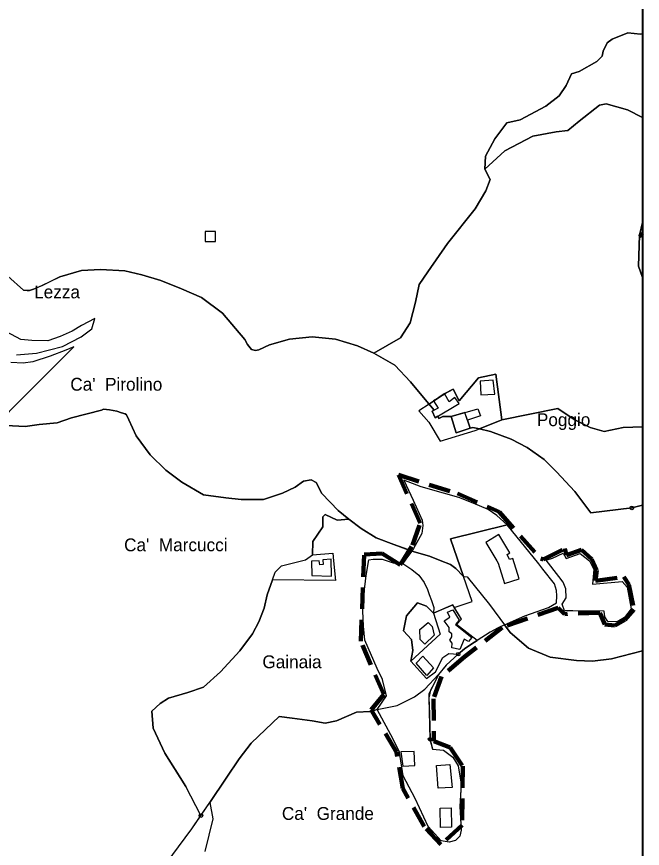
# Model space of a CAD drawing. Extents: x 652791 to 656927, y 889884 to 892405.
# Drawn here: x 656439 to 656927, y 891133 to 891781 of the extents above; entities that cross this region are included whole.
import ezdxf
from ezdxf.enums import TextEntityAlignment as Align

# ---------------------------------------------------------------- set-up
doc = ezdxf.new("R2010")
doc.units = 0
doc.header["$LTSCALE"] = 5.6
doc.header["$PDMODE"] = 32
doc.header["$PDSIZE"] = 2.8
doc.linetypes.add('MEDIUM_DASHED', pattern=[4.5, 3, -1.5])
for name, color, linetype, lineweight in [('2', 7, 'Continuous', 25), ('29', 7, 'Continuous', 25), ('3', 7, 'Continuous', 25), ('35', 7, 'Continuous', 25), ('36', 7, 'Continuous', 25), ('37', 7, 'Continuous', 25), ('55', 7, 'Continuous', 25), ('6', 7, 'Continuous', 25), ('61', 7, 'Continuous', 35), ('7', 7, 'MEDIUM_DASHED', 100), ('9', 7, 'Continuous', 25)]:
    doc.layers.add(name, color=color, linetype=linetype, lineweight=lineweight)
doc.layers.add('60', color=7, linetype='Continuous')

msp = doc.modelspace()

# ---------------------------------------------------------------- linework, layer by layer
at = {"layer": '2'}
for points in [[(656740.56, 891189.29), (656737.49, 891207.75), (656732.75, 891217.93), (656720.19, 891241.12), (656735.76, 891244.14), (656749.25, 891250.78), (656757.25, 891256.73), (656767.97, 891268.36), (656760.44, 891253.02), (656761.35, 891217.78)], [(656761.35, 891217.78), (656763.34, 891210.01), (656771.87, 891209.25), (656779.26, 891203.94), (656783.31, 891197.18), (656785.59, 891182.99), (656784.57, 891165.38), (656785.62, 891147.05)], [(656770.04, 891138.59), (656765.02, 891141.89), (656759.91, 891149.86), (656749.79, 891171.53), (656740.56, 891189.29)], [(656785.62, 891147.05), (656784.72, 891142.27), (656781.31, 891139.05), (656776.2, 891137.53), (656770.04, 891138.59)]]:
    msp.add_lwpolyline(points, dxfattribs=at)
for points in [[(656738.67, 891207.99), (656740.09, 891196.86), (656749.55, 891197.33), (656749.08, 891208.23)], [(656766.35, 891197.33), (656776.79, 891198.03), (656778.55, 891180.27), (656767.77, 891179.58)], [(656769.22, 891164.23), (656777.75, 891164.45), (656778.13, 891149.3), (656769.6, 891149.09)]]:
    msp.add_lwpolyline(points, close=True, dxfattribs=at)
at = {"layer": '29'}
msp.add_line((656807.7, 891322.7), (656819.4, 891306.96), dxfattribs=at)
for points in [[(656819.4, 891306.96), (656835.17, 891313.87), (656853.61, 891320.46), (656860.03, 891324.08), (656860.27, 891329.63), (656860.03, 891333.73), (656858.34, 891338.79), (656849.18, 891350.37), (656846.22, 891354.57), (656821.47, 891384.93), (656777.34, 891374.06), (656787.49, 891344.56)], [(656727.47, 891251.62), (656724.29, 891264.49), (656720.11, 891273.05), (656710.65, 891295.12), (656709.54, 891305.81), (656709, 891317.83), (656709.91, 891330.03), (656711.55, 891345.51), (656713.71, 891357.68)], [(656713.71, 891357.68), (656717.15, 891358.12), (656724.09, 891358.12), (656732.71, 891355.24), (656740.12, 891354.8), (656747.19, 891350.13), (656752.55, 891345.78), (656756.76, 891339.83), (656759.51, 891334.61), (656760.82, 891330.55), (656762.56, 891325.9), (656764.3, 891320.39), (656764.14, 891316.1), (656758.53, 891321.49), (656751.59, 891324.18), (656743.09, 891313.87), (656740.71, 891302.37), (656746.84, 891295.43), (656748.11, 891286.88), (656746.55, 891278.54), (656758.59, 891265.27)], [(656798.11, 891294.88), (656782.04, 891307.3), (656785.87, 891311.45), (656780.32, 891320.48), (656794.15, 891325.18), (656787.49, 891344.56)], [(656787.49, 891344.56), (656790.2, 891344.37), (656807.7, 891322.7)], [(656787.49, 891344.56), (656790.2, 891344.37), (656807.7, 891322.7), (656819.4, 891306.96), (656814.47, 891304.73)], [(656814.47, 891304.73), (656808.33, 891301.36), (656798.11, 891294.88)], [(656758.59, 891265.27), (656765.69, 891270.47), (656771.39, 891281.47), (656776.11, 891284.65), (656783.32, 891284.1), (656774.03, 891275.5), (656767.97, 891268.36), (656764.29, 891260.63)], [(656764.29, 891260.63), (656761.83, 891256.08), (656760.5, 891250.2), (656760.89, 891237.45), (656761.39, 891217.72), (656763.34, 891210.01)], [(656784.72, 891142.27), (656781.31, 891139.05), (656776.2, 891137.53), (656770.04, 891138.59), (656759.91, 891149.86), (656749.79, 891171.53), (656740.56, 891189.29), (656737.49, 891207.75), (656732.75, 891217.93), (656720.19, 891241.12), (656727.47, 891251.62)], [(656763.34, 891210.01), (656771.87, 891209.25), (656779.27, 891203.94), (656783.31, 891197.18), (656785.59, 891182.92), (656784.57, 891165.38), (656785.62, 891147.05), (656784.72, 891142.27)]]:
    msp.add_lwpolyline(points, dxfattribs=at)
at = {"layer": '3'}
for points in [[(656800, 891459.73), (656817.28, 891466.65), (656812.54, 891502.27), (656799.22, 891499.41), (656784.06, 891481.42), (656779.45, 891490.65), (656772.53, 891486.96), (656760.61, 891478.91), (656764.7, 891474.27)], [(656767.47, 891469.51), (656765.29, 891468.22), (656762.96, 891473.4), (656764.7, 891474.27), (656760.61, 891478.91), (656752.69, 891473.57), (656760.54, 891464.8), (656769.3, 891450.03)], [(656764.7, 891474.27), (656762.96, 891473.4), (656765.29, 891468.22), (656767.47, 891469.51)], [(656777.78, 891469.38), (656771.27, 891469.38), (656768.32, 891467.63), (656767.47, 891469.51)], [(656767.47, 891469.51), (656768.32, 891467.63), (656771.27, 891469.38), (656777.78, 891469.38)], [(656792.72, 891460.16), (656790.62, 891466.46), (656792.72, 891460.16), (656788.61, 891472.47), (656777.78, 891469.38)], [(656777.78, 891469.38), (656781.86, 891456.54), (656792.72, 891460.16)], [(656769.3, 891450.03), (656796.52, 891458.34), (656800, 891459.73)], [(656800, 891459.73), (656794.67, 891460.7), (656792.72, 891460.16), (656792.72, 891460.16)], [(656792.72, 891460.16), (656794.67, 891460.7), (656800, 891459.73)]]:
    msp.add_lwpolyline(points, dxfattribs=at)
for points in [[(656800.49, 891496.81), (656801, 891486.05), (656811.92, 891486.55), (656810.58, 891497.48)], [(656764.15, 891481.41), (656767.7, 891475.77), (656762.96, 891473.4), (656765.29, 891468.22), (656784.01, 891479.33), (656780.75, 891484.08), (656776.3, 891480.82), (656773.04, 891486.75)], [(656777.78, 891469.38), (656798.67, 891475.34), (656800.65, 891469.73), (656790.62, 891466.46), (656792.72, 891460.16), (656781.86, 891456.54)], [(656686.23, 891356.92), (656687.65, 891341.43), (656638.69, 891342.07), (656640.82, 891347.88), (656645.78, 891353.04), (656664.23, 891357.56), (656669.91, 891361.43), (656685.63, 891362.77)], [(656669.09, 891356.59), (656669.41, 891345.31), (656684.6, 891344.99), (656684.27, 891358.06), (656677.9, 891357.57), (656678.07, 891353.97), (656675.46, 891353.81), (656675.13, 891356.75)], [(656783.32, 891284.1), (656788.17, 891288.25), (656793.95, 891292.27), (656798.11, 891294.88), (656782.04, 891307.3), (656785.87, 891311.45), (656779.15, 891322.44), (656764.14, 891316.1), (656769.29, 891299.57), (656746.55, 891278.54), (656758.59, 891265.27), (656765.69, 891270.47), (656771.39, 891281.47), (656776.11, 891284.65)], [(656772.49, 891310), (656776.73, 891313.03), (656775.03, 891316.91), (656779.03, 891318.6), (656784.12, 891310.72), (656781.33, 891307.33), (656793.91, 891296.98), (656791.39, 891293.99), (656787.87, 891295.81), (656784.6, 891287.69), (656778.39, 891288.94), (656778.67, 891292.78), (656776.73, 891294.96), (656778.42, 891297.63), (656778.42, 891299.93), (656776.24, 891301.39), (656776.24, 891304.9)], [(656753.34, 891303.21), (656759.89, 891308.9), (656763.16, 891305.63), (656764.49, 891298.84), (656757.34, 891291.93), (656753.83, 891295.45)], [(656755.77, 891282.59), (656764.18, 891273.55), (656758.8, 891267.44), (656750.68, 891277.02)]]:
    msp.add_lwpolyline(points, close=True, dxfattribs=at)
at = {"layer": '35'}
for p, q in [((656926.84, 891400.08), (656926.84, 891461.14)), ((656918.71, 891398.05), (656926.84, 891400.08))]:
    msp.add_line(p, q, dxfattribs=at)
for points in [[(656439.23, 891517.31), (656454.68, 891518.69), (656474.94, 891523.84), (656489.57, 891531.26), (656497.95, 891537.46), (656500.12, 891545.63), (656489.78, 891540.14), (656482.63, 891535.67), (656473.18, 891531.71), (656463.61, 891528.13), (656451.23, 891528.51), (656442.51, 891529.38), (656431.26, 891535.26)], [(656422.82, 891464.06), (656433.72, 891473.33), (656483.94, 891523.47)], [(656483.94, 891523.47), (656477.61, 891520.97), (656465.41, 891516.18), (656451.93, 891511.82), (656444.38, 891510.79), (656434.76, 891511.47)], [(656926.84, 891461.14), (656911.89, 891460.76), (656897.05, 891457.61), (656886.26, 891460.76), (656873.66, 891467.05), (656861.07, 891475.6), (656817.28, 891466.65)], [(656817.29, 891466.65), (656800.01, 891459.73), (656800, 891459.73), (656808.47, 891457.61), (656824.63, 891451.61), (656837.2, 891445.05), (656850.44, 891435.83)], [(656850.44, 891435.83), (656860.01, 891426.26), (656874.25, 891410.91), (656886.75, 891394.24), (656918.71, 891398.05)]]:
    msp.add_lwpolyline(points, dxfattribs=at)
msp.add_point((656918.71, 891398.05), dxfattribs=at)
at = {"layer": '36', "lineweight": 120}
msp.add_line((656924.53, 891609.56), (656926.84, 891611.87), dxfattribs=at)
at = {"layer": '36'}
for points in [[(656926.84, 891702.14), (656926.84, 891767.45), (656925.37, 891767.13), (656915.39, 891768.1), (656903.42, 891763.26), (656899.43, 891760.35), (656896.22, 891754.03), (656895.44, 891750.14), (656891.45, 891745.84), (656877.48, 891738.1), (656871.5, 891736.16), (656867.47, 891727.2), (656862.03, 891719.04), (656851.54, 891711), (656831.73, 891700.38), (656821.24, 891698.05), (656811.92, 891685.61), (656804.53, 891672), (656804.15, 891661.89), (656819.62, 891676.16), (656841.57, 891687.77), (656859.7, 891691.05), (656868.64, 891692.21), (656877.48, 891699.39), (656893.44, 891711.97), (656898.55, 891712.82), (656915.25, 891708.15)], [(656926.84, 891577.54), (656926.84, 891620.46), (656924.56, 891610.59), (656923.78, 891586.49)]]:
    msp.add_lwpolyline(points, close=True, dxfattribs=at)
for points in [[(656550.54, 891114), (656575.8, 891148.01), (656589.8, 891168.48), (656592.15, 891155.89)], [(656592.15, 891155.89), (656585.83, 891130.41)]]:
    msp.add_lwpolyline(points, dxfattribs=at)
at = {"layer": '37'}
for p, q in [((656926.84, 891577.54), (656923.78, 891586.49)), ((656926.84, 890923.77), (656926.84, 891286.61)), ((656761.35, 891217.78), (656763.34, 891210.01)), ((656565.91, 891189.28), (656571.03, 891181.08)), ((656582.84, 891158.29), (656589.8, 891168.48))]:
    msp.add_line(p, q, dxfattribs=at)
for points in [[(656926.84, 891767.45), (656926.84, 891892.65), (656893.79, 891869.75), (656871.74, 891854.2), (656848.69, 891836.7), (656829.71, 891821.36), (656816.63, 891843.5), (656815.63, 891856.14), (656818.63, 891875.58)], [(656717.72, 891518.6), (656738.27, 891530.53), (656745.89, 891542.32), (656750.05, 891558.28), (656752.83, 891572.15), (656759.76, 891581.86), (656775.01, 891604.06), (656796.51, 891631.12), (656804.83, 891645), (656808.29, 891654.01), (656804.15, 891661.89), (656804.53, 891672), (656811.92, 891685.61), (656821.24, 891698.05), (656831.73, 891700.38), (656851.54, 891711), (656862.03, 891719.04), (656867.47, 891727.2), (656871.5, 891736.16), (656877.48, 891738.1), (656891.45, 891745.84), (656895.44, 891750.14), (656896.22, 891754.03), (656899.43, 891760.35), (656903.42, 891763.26), (656915.39, 891768.1), (656925.37, 891767.13), (656926.84, 891767.45)], [(656923.78, 891586.49), (656924.56, 891610.59), (656926.84, 891620.46), (656926.84, 891702.14), (656915.25, 891708.15), (656898.55, 891712.82), (656893.44, 891711.97), (656877.48, 891699.39), (656868.64, 891692.21), (656859.7, 891691.05), (656841.57, 891687.77), (656819.62, 891676.16), (656804.15, 891661.89)], [(656804.15, 891661.89), (656808.29, 891654.01), (656804.83, 891645), (656796.51, 891631.12), (656775.01, 891604.06), (656759.76, 891581.86), (656752.83, 891572.15), (656750.05, 891558.28), (656745.89, 891542.32), (656738.27, 891530.53), (656717.72, 891518.6)], [(656422.4, 891596.41), (656422.23, 891585.59), (656432.3, 891578.53), (656444.62, 891567.63)], [(656444.62, 891567.63), (656447.38, 891567.41), (656449.23, 891567.57), (656452.44, 891568.46), (656458.87, 891571.22), (656472.84, 891578.01), (656489.88, 891582.98), (656504.64, 891583.68), (656523.56, 891582.71), (656536.76, 891579.54), (656551.68, 891575.22), (656567.76, 891568.86), (656583.45, 891561.99), (656599.79, 891549.91), (656616.97, 891529.28), (656619.08, 891525.47), (656622.25, 891521.54), (656625.51, 891520.71), (656628.02, 891521.13), (656636.41, 891525.21), (656651.98, 891529.46), (656669.48, 891531.41), (656687.78, 891529.45), (656704.96, 891524.46), (656717.72, 891518.6)], [(656817.28, 891466.65), (656861.07, 891475.6), (656873.66, 891467.05), (656886.26, 891460.76), (656897.05, 891457.61), (656911.89, 891460.76), (656926.84, 891461.14), (656926.84, 891577.54)], [(656717.72, 891518.6), (656733.89, 891509.27), (656746.14, 891496.4), (656760.1, 891479.5), (656760.5, 891478.84), (656772.54, 891486.96), (656779.46, 891490.65), (656784.07, 891481.42), (656799.23, 891499.41), (656812.54, 891502.27), (656817.29, 891466.65)], [(656698.25, 891389.17), (656689.83, 891396.11), (656677.16, 891409.32), (656672.55, 891417.89), (656668.88, 891420), (656662.88, 891418.78), (656656.24, 891414.12), (656646.33, 891409.61), (656631.59, 891404.69), (656614.12, 891404.69), (656602.4, 891405.95), (656584.95, 891408.23), (656567.94, 891418.06), (656555.42, 891427.45), (656543.42, 891439.46), (656532.44, 891454.11), (656526.8, 891466.81), (656524.98, 891470.61), (656523.95, 891471.33), (656521.12, 891472.25), (656517.45, 891473.36), (656511.53, 891474.41), (656506.87, 891474.96), (656505.37, 891474.15), (656482.13, 891468.34), (656470.86, 891464.44), (656456.84, 891462.98), (656445.81, 891461.61), (656431.13, 891462.3)], [(656698.25, 891389.17), (656689.07, 891388.58), (656679.77, 891393.03), (656677.75, 891391.01), (656677.75, 891383.33), (656670.07, 891372), (656669.91, 891361.43), (656685.63, 891362.77), (656686.23, 891356.92), (656687.65, 891341.43), (656638.69, 891342.07)], [(656669.91, 891361.43), (656670.07, 891372), (656677.75, 891383.33), (656677.75, 891391.01), (656679.77, 891393.03), (656689.07, 891388.58), (656698.25, 891389.17)], [(656744.22, 891365.55), (656733.16, 891369.58), (656719.33, 891374.83), (656707.76, 891382.14), (656698.25, 891389.17)], [(656713.71, 891357.67), (656717.15, 891358.11), (656724.09, 891358.11), (656732.71, 891355.23), (656740.12, 891354.79), (656747.12, 891364.41), (656744.22, 891365.55)], [(656575.8, 891148.01), (656582.84, 891158.29), (656571.03, 891181.08), (656554.86, 891206.97), (656545.56, 891226.39), (656544.75, 891239.73), (656551.22, 891245.8), (656557.69, 891249.85), (656572.65, 891254.3), (656584.77, 891258.34), (656598.11, 891270.47), (656613.07, 891286.65), (656623.18, 891300), (656628.03, 891309.3), (656632.07, 891319.82), (656634.49, 891330.34), (656638.69, 891342.07), (656640.82, 891347.88), (656645.78, 891353.04), (656664.23, 891357.56), (656669.91, 891361.43)], [(656727.47, 891251.61), (656724.29, 891264.48), (656720.11, 891273.04), (656710.65, 891295.11), (656709.54, 891305.8), (656709, 891317.82), (656709.91, 891330.02), (656711.55, 891345.5), (656713.71, 891357.67)], [(656638.69, 891342.07), (656634.49, 891330.34), (656632.07, 891319.82), (656628.03, 891309.3)], [(656628.03, 891309.3), (656623.18, 891300), (656613.07, 891286.65), (656598.11, 891270.47), (656584.77, 891258.34)], [(656814.47, 891304.73), (656808.33, 891301.36), (656798.11, 891294.88), (656793.95, 891292.27), (656788.17, 891288.25), (656783.32, 891284.1)], [(656926.84, 891286.61), (656902.91, 891280.49), (656887.97, 891278.65), (656875.5, 891279.28), (656854.97, 891281.74), (656838.16, 891288.7), (656823.81, 891301.01), (656819.4, 891306.96), (656814.47, 891304.73)], [(656783.32, 891284.1), (656774.03, 891275.5), (656767.97, 891268.36), (656764.29, 891260.63)], [(656764.29, 891260.63), (656760.44, 891253.02), (656760.5, 891250.2), (656761.35, 891217.78)], [(656584.77, 891258.34), (656572.65, 891254.3), (656557.69, 891249.85), (656551.22, 891245.8), (656544.75, 891239.73), (656545.56, 891226.39), (656554.86, 891206.97), (656565.91, 891189.28)], [(656633.28, 891225.41), (656643.88, 891235.46), (656653.93, 891234.34), (656669.55, 891232.11), (656679.59, 891230.44), (656688.52, 891232.11), (656704.14, 891238.81), (656714.74, 891239.37), (656720.19, 891241.11), (656727.47, 891251.61)], [(656720.19, 891241.11), (656714.74, 891239.37), (656704.14, 891238.81), (656688.52, 891232.11), (656679.59, 891230.44), (656669.55, 891232.11), (656653.93, 891234.34), (656643.88, 891235.46), (656633.28, 891225.41), (656622.12, 891214.8), (656612.64, 891202.52), (656602.6, 891187.45), (656589.8, 891168.48), (656592.15, 891155.89), (656585.83, 891130.41)], [(656770.04, 891138.59), (656765.02, 891141.89), (656759.91, 891149.86), (656749.79, 891171.53), (656740.56, 891189.29), (656737.49, 891207.75), (656732.75, 891217.93), (656720.19, 891241.11)], [(656589.8, 891168.48), (656602.6, 891187.45), (656612.64, 891202.52), (656622.12, 891214.8), (656633.28, 891225.41)], [(656763.34, 891210.01), (656771.87, 891209.25), (656779.26, 891203.94), (656783.31, 891197.18), (656785.59, 891182.99), (656784.57, 891165.38), (656785.63, 891147.05)], [(656346.76, 891030.15), (656359.82, 891039.27), (656374.91, 891047.18), (656393.59, 891057.96), (656408.69, 891068.03), (656423.06, 891083.85), (656441.02, 891098.23), (656451.08, 891102.54), (656460.42, 891102.54), (656471.2, 891099.67), (656475.55, 891098.58), (656489.19, 891092.99), (656505.69, 891087.49), (656521.15, 891086.99), (656530.43, 891088.49), (656539.2, 891093.99), (656550.54, 891114), (656575.8, 891148.01)], [(656785.63, 891147.05), (656784.72, 891142.27), (656781.31, 891139.05), (656776.2, 891137.53), (656770.04, 891138.59)]]:
    msp.add_lwpolyline(points, dxfattribs=at)
for p in [(656783.32, 891284.1), (656761.35, 891217.78), (656582.84, 891158.29)]:
    msp.add_point(p, dxfattribs=at)
at = {"layer": '55'}
for p, q in [((656444.62, 891567.62), (656432.3, 891578.53)), ((656926.84, 891286.61), (656926.84, 891400.08))]:
    msp.add_line(p, q, dxfattribs=at)
for points in [[(656886.75, 891394.24), (656874.25, 891410.91), (656860.01, 891426.26), (656850.44, 891435.83), (656837.2, 891445.04), (656824.63, 891451.61), (656808.47, 891457.61), (656800, 891459.73), (656794.67, 891460.7), (656792.72, 891460.16), (656790.62, 891466.46), (656788.61, 891472.47), (656777.78, 891469.38), (656771.27, 891469.38), (656768.32, 891467.63), (656767.47, 891469.51), (656765.29, 891468.22), (656762.96, 891473.4), (656764.7, 891474.27), (656760.09, 891479.49), (656746.14, 891496.39), (656733.88, 891509.27), (656717.72, 891518.6), (656704.96, 891524.45), (656687.78, 891529.44), (656669.47, 891531.41), (656651.98, 891529.46), (656636.41, 891525.21), (656628.01, 891521.12), (656625.51, 891520.7), (656622.25, 891521.54), (656619.07, 891525.47), (656616.97, 891529.27), (656599.79, 891549.9), (656583.45, 891561.99), (656567.76, 891568.86), (656551.68, 891575.22), (656536.76, 891579.54), (656523.56, 891582.71), (656504.64, 891583.68), (656489.88, 891582.98), (656472.83, 891578.01), (656458.87, 891571.21), (656452.43, 891568.45), (656449.23, 891567.56), (656447.38, 891567.4), (656444.62, 891567.62)], [(656431.13, 891462.3), (656445.81, 891461.61), (656456.84, 891462.98), (656470.86, 891464.44), (656482.13, 891468.34), (656505.37, 891474.15), (656506.87, 891474.96), (656511.53, 891474.41), (656517.45, 891473.36), (656521.12, 891472.25), (656523.95, 891471.33), (656524.98, 891470.61), (656526.8, 891466.81), (656532.44, 891454.11), (656543.42, 891439.46), (656555.42, 891427.45), (656567.94, 891418.06), (656584.95, 891408.23), (656602.4, 891405.95), (656614.12, 891404.69), (656631.59, 891404.69), (656646.33, 891409.61), (656656.24, 891414.12), (656662.88, 891418.78), (656668.88, 891420), (656672.55, 891417.89), (656677.16, 891409.32), (656689.83, 891396.11), (656698.25, 891389.17), (656707.76, 891382.14), (656719.33, 891374.83), (656733.16, 891369.58), (656747.12, 891364.41)], [(656926.84, 891400.08), (656918.71, 891398.05), (656886.75, 891394.24)], [(656747.12, 891364.41), (656760.93, 891360.38), (656777.26, 891353.95), (656781.5, 891350.98), (656787.49, 891344.56), (656790.2, 891344.37), (656807.7, 891322.7), (656823.81, 891301.01)], [(656823.81, 891301.01), (656838.16, 891288.7), (656854.97, 891281.74), (656875.5, 891279.28), (656887.97, 891278.65), (656902.91, 891280.49), (656926.84, 891286.61)]]:
    msp.add_lwpolyline(points, dxfattribs=at)
at = {"layer": '6'}
for points in [[(656586.18, 891605.5), (656594.18, 891605.5), (656594.18, 891613.5), (656586.18, 891613.5)], [(656815.02, 891377.28), (656804.75, 891371.06), (656813.35, 891356.86), (656814.45, 891354.97), (656819.48, 891339.15), (656830.92, 891342.79), (656825.88, 891358.61), (656823.41, 891357.82), (656821.39, 891361.73), (656823.62, 891363.08)]]:
    msp.add_lwpolyline(points, close=True, dxfattribs=at)
at = {"layer": '61', "lineweight": 40}
msp.add_lwpolyline([(654894.04, 892404.68), (656926.84, 892404.68), (656926.84, 889884.41), (654894.04, 889884.41)], close=True, dxfattribs=at)
at = {"layer": '7'}
for points in [[(656861.13, 891320.28), (656817.52, 891304.98), (656788.29, 891282.04), (656770.31, 891266.74), (656764.01, 891249.2), (656764.46, 891216.36), (656777.05, 891211.41), (656786.84, 891196.73), (656786.49, 891150.82), (656769.86, 891135.75), (656756.72, 891149.94), (656740.18, 891179.47), (656735.24, 891207.81), (656715.45, 891240.65), (656725.39, 891252.7), (656707.44, 891294.12), (656710.06, 891361.67), (656724, 891362.57), (656738.23, 891353.65), (656747.64, 891368.91), (656753.81, 891386.12), (656736.76, 891423.71), (656782.7, 891409.18), (656815.27, 891394.96), (656847.64, 891358.52), (656849.6, 891357.89)], [(656849.6, 891357.89), (656866.43, 891366.31), (656867.72, 891361.12), (656879.41, 891365.34), (656887.52, 891358.19), (656891.42, 891349.43), (656890.44, 891341.31), (656912.51, 891344.23), (656916.41, 891338.39), (656920.3, 891318.9), (656913.16, 891310.78), (656905.37, 891306.56), (656897.58, 891307.21), (656893.69, 891316.3), (656866.1, 891315.33), (656861.13, 891320.28)]]:
    msp.add_lwpolyline(points, dxfattribs=at)
at = {"layer": '9'}
for points in [[(656787.49, 891344.56), (656777.34, 891374.06), (656821.47, 891384.93), (656813.33, 891392.19), (656806.72, 891396.75), (656795.04, 891401.81), (656783.86, 891406.1), (656771.97, 891409.43), (656754.48, 891414.43), (656740.87, 891419.63), (656748.38, 891404.18), (656755.35, 891388.6), (656755.8, 891384.39), (656754.9, 891378.12), (656748.6, 891366.51), (656747.12, 891364.41)], [(656787.49, 891344.56), (656787.17, 891344.96), (656781.5, 891350.98), (656777.26, 891353.95), (656769.21, 891357.21), (656760.93, 891360.38), (656747.12, 891364.41), (656743.94, 891359.9), (656740.12, 891354.8)], [(656747.12, 891364.41), (656760.93, 891360.38), (656769.21, 891357.21), (656777.26, 891353.95), (656781.5, 891350.98), (656787.17, 891344.96), (656787.49, 891344.56)], [(656740.12, 891354.8), (656747.19, 891350.13), (656752.55, 891345.78), (656756.76, 891339.83)], [(656768.84, 891318.08), (656779.15, 891322.44), (656780.32, 891320.48), (656794.15, 891325.18), (656787.49, 891344.56)], [(656756.76, 891339.83), (656759.51, 891334.61), (656760.82, 891330.55)], [(656760.82, 891330.55), (656762.56, 891325.9), (656764.3, 891320.39), (656764.14, 891316.1), (656768.84, 891318.08)]]:
    msp.add_lwpolyline(points, dxfattribs=at)
for points in [[(656851.97, 891357.43), (656856.71, 891358.99), (656865.21, 891362.8), (656867.4, 891358.67), (656878.44, 891362.41), (656885.65, 891356.8), (656889.03, 891349.99), (656888.03, 891338.56), (656911.21, 891340.68), (656914.9, 891336.24), (656918.2, 891319.42), (656913, 891312.79), (656907.32, 891309.32), (656899.91, 891309.64), (656897.71, 891313.3), (656897.08, 891317.68), (656872.65, 891317.99), (656866.18, 891317.84), (656864.47, 891323.11), (656867.41, 891328.07), (656867.1, 891334.95), (656865.12, 891340.14), (656861.74, 891344.53)], [(656764.14, 891316.1), (656769.29, 891299.57), (656746.55, 891278.54), (656748.11, 891286.88), (656746.84, 891295.43), (656740.71, 891302.37), (656743.09, 891313.87), (656751.59, 891324.18), (656758.53, 891321.49)]]:
    msp.add_lwpolyline(points, close=True, dxfattribs=at)

# ---------------------------------------------------------------- texts
at = {"layer": '60'}
for s, p in [('Lezza', (656470.79, 891561.34)), ("Ca'  Pirolino", (656516.94, 891489.4)), ('Poggio', (656865.49, 891461.77)), ("Ca'  Marcucci", (656563.31, 891364.27)), ('Gainaia', (656653.82, 891273.17)), ("Ca'  Grande", (656681.81, 891154.99))]:
    msp.add_text(s, height=10, dxfattribs=at).set_placement(p, align=Align.CENTER)

doc.saveas('drawing.dxf')
